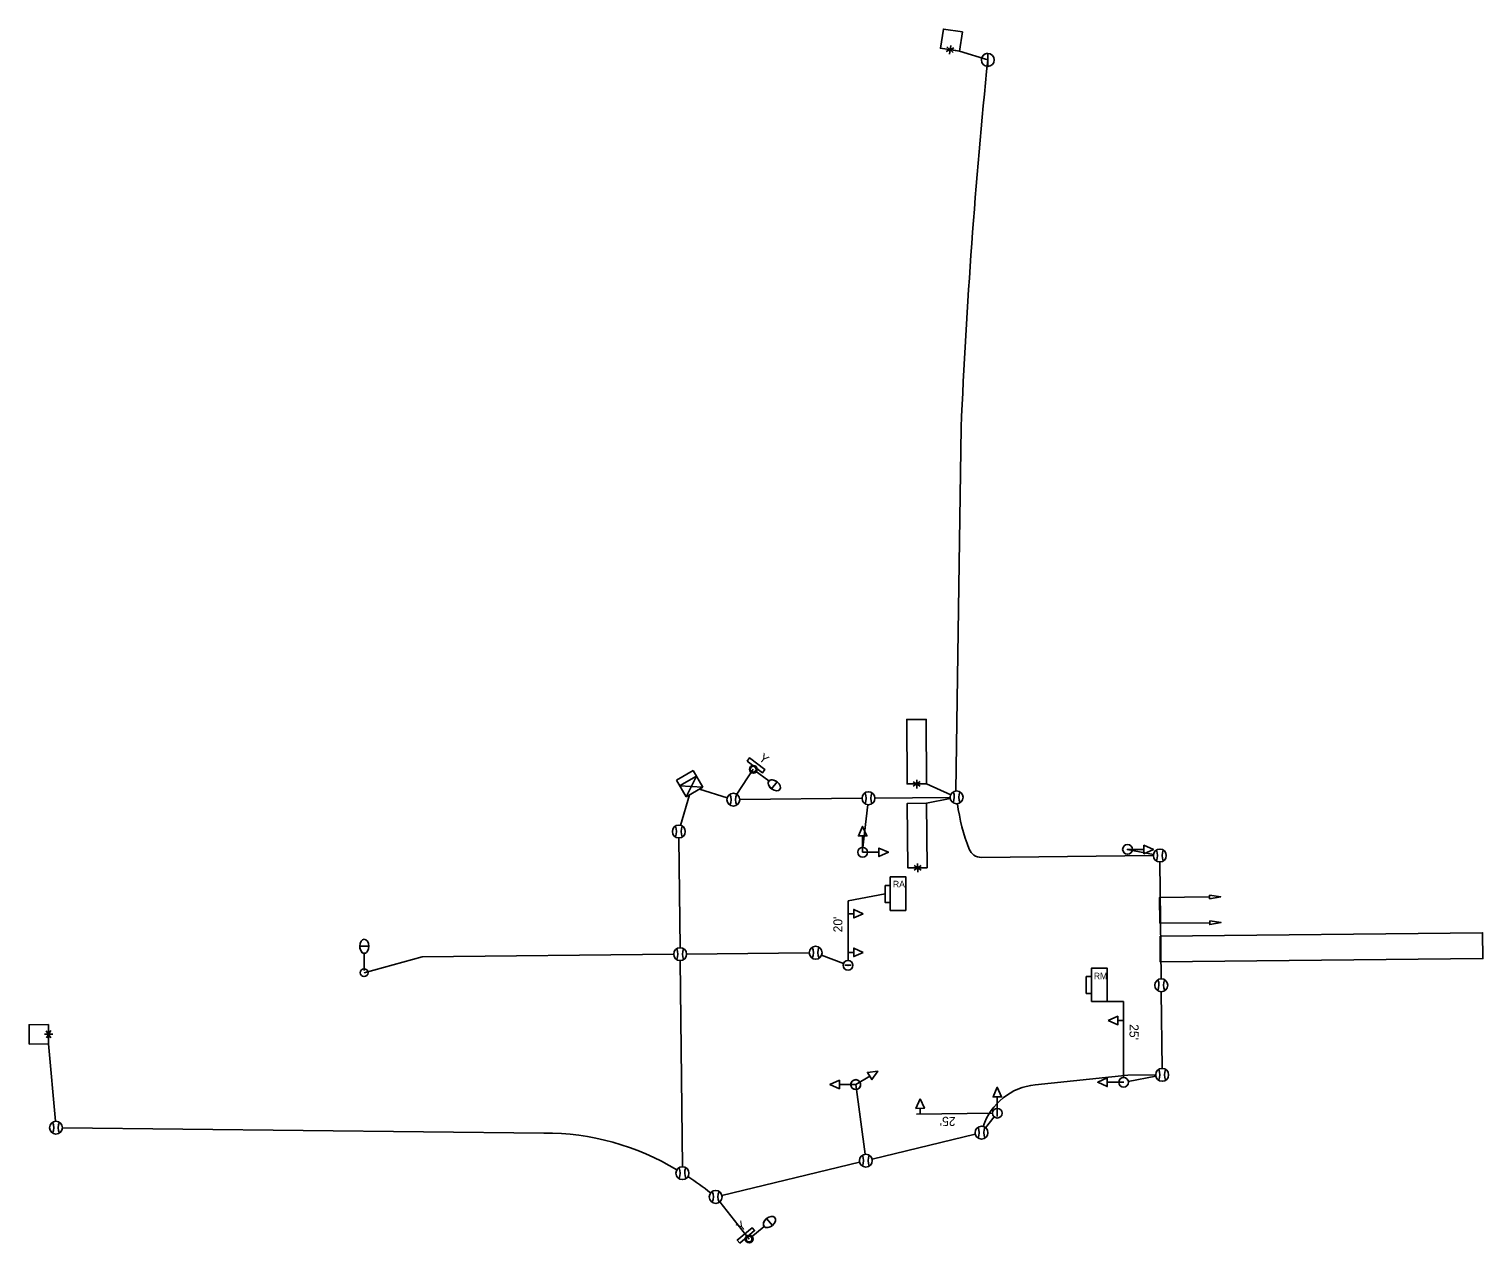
# Model space of a CAD drawing. Extents: x 596176 to 605330, y 332416 to 402398.
# Drawn here: x 602359.2 to 602809.7, y 387543.7 to 387920.7 of the extents above; entities that cross this region are included whole.
import ezdxf

# ---------------------------------------------------------------- set-up
doc = ezdxf.new("R2010")
doc.units = 0
for name, color, linetype in [('P_LTG', 7, 'Continuous'), ('P_SIG', 7, 'Continuous'), ('P_SIG_Bold', 7, 'Continuous'), ('P_SIG_Conduit', 7, 'Continuous'), ('P_SIG_Loops', 7, 'Continuous')]:
    doc.layers.add(name, color=color, linetype=linetype)

# ---------------------------------------------------------------- blocks, each defined once
blk = doc.blocks.new('_U309')
at = {"layer": 'P_SIG_Bold'}
for p, q in [((-3, 0), (-0.1, 0)), ((-0.1, 0.1), (0.1, -0.1)), ((0.1, 0.1), (-0.1, -0.1))]:
    blk.add_line(p, q, dxfattribs=at)
blk.add_circle((0, 0), 0.114, dxfattribs=at)
blk.add_text("40'", height=0.213, dxfattribs=at).set_placement((-1.9, 0.1))
blk = doc.blocks.new('_U321')
at = {"layer": 'P_LTG'}
for p, q in [((4.3, 25.1), (-4.1, 25.1)), ((0, 2.3), (0, 18.4))]:
    blk.add_line(p, q, dxfattribs=at)
blk.add_circle((0, 0.1), 3.68, dxfattribs=at)
blk.add_ellipse((0.1, 25.1), major_axis=(0, 6.65), ratio=0.636439, dxfattribs=at)
blk.add_ellipse((0.1, 25.1), major_axis=(0, 6.65), ratio=0.636439, start_param=1.570796, end_param=4.712389, dxfattribs=at)
blk = doc.blocks.new('_U322')
at = {"layer": 'P_LTG'}
for p, q in [((4.3, 25.1), (-4.1, 25.1)), ((0, 2.3), (0, 18.4))]:
    blk.add_line(p, q, dxfattribs=at)
blk.add_circle((0, 0.1), 3.68, dxfattribs=at)
blk.add_ellipse((0.1, 25.1), major_axis=(0, 6.65), ratio=0.636439, dxfattribs=at)
blk.add_ellipse((0.1, 25.1), major_axis=(0, 6.65), ratio=0.636439, start_param=1.570796, end_param=4.712389, dxfattribs=at)

msp = doc.modelspace()

# ---------------------------------------------------------------- linework, layer by layer
at = {"layer": 'P_SIG'}
for p, q in [((602656.31, 387913.11), (602656.29, 387909.11)), ((602581.71, 387693.74), (602582.44, 387694.7)), ((602586.49, 387690.11), (602581.71, 387693.74)), ((602582.44, 387694.7), (602587.22, 387691.06)), ((602559.78, 387687.78), (602564.96, 387690.8)), ((602562.8, 387682.59), (602559.78, 387687.78)), ((602560.79, 387686.05), (602565.97, 387689.07)), ((602562.8, 387682.59), (602565.97, 387689.07)), ((602564.96, 387690.8), (602567.99, 387685.62)), ((602587.22, 387691.06), (602586.49, 387690.11)), ((602567.99, 387685.62), (602560.79, 387686.05)), ((602567.99, 387685.62), (602562.8, 387682.59)), ((602617.5, 387670.51), (602617.49, 387665.46)), ((602622.55, 387665.44), (602617.49, 387665.46)), ((602704.66, 387666.31), (602699.6, 387666.33)), ((602624.45, 387652.53), (602612.98, 387650.41)), ((602614.75, 387646.41), (602612.98, 387646.41)), ((602614.77, 387634.41), (602612.99, 387634.41)), ((602693.26, 387619.22), (602698.37, 387619.13)), ((602696.6, 387613.29), (602698.37, 387613.31)), ((602610.31, 387593.44), (602615.37, 387593.43)), ((602619.69, 387596.07), (602615.37, 387593.43)), ((602693.31, 387594.14), (602698.37, 387594.13)), ((602659.25, 387589.61), (602659.24, 387584.55)), ((602635.33, 387586.07), (602635.35, 387584.3)), ((602578.65, 387545.19), (602583.24, 387549.05)), ((602584.01, 387548.13), (602579.42, 387544.27)), ((602583.24, 387549.05), (602584.01, 387548.13)), ((602579.42, 387544.27), (602578.65, 387545.19))]:
    msp.add_line(p, q, dxfattribs=at)
for points in [[(602656.29, 387909.11), (602656.31, 387913.11)], [(602617.5, 387673.47), (602618.82, 387670.51), (602616.18, 387670.51), (602617.5, 387673.47)], [(602618.82, 387670.51), (602617.5, 387673.47), (602616.18, 387670.51), (602618.82, 387670.51)], [(602625.51, 387665.44), (602622.55, 387664.13), (602622.55, 387666.76), (602625.51, 387665.44)], [(602622.55, 387664.13), (602625.51, 387665.44), (602622.55, 387666.76), (602622.55, 387664.13)], [(602707.62, 387666.31), (602704.66, 387665), (602704.66, 387667.63), (602707.62, 387666.31)], [(602704.66, 387665), (602707.62, 387666.31), (602704.66, 387667.63), (602704.66, 387665)], [(602622.21, 387597.62), (602620.38, 387594.95), (602619, 387597.19), (602622.21, 387597.62)], [(602620.38, 387594.95), (602622.21, 387597.62), (602619, 387597.19), (602620.38, 387594.95)], [(602607.35, 387593.44), (602610.31, 387594.76), (602610.31, 387592.12), (602607.35, 387593.44)], [(602610.31, 387594.76), (602607.35, 387593.44), (602610.31, 387592.12), (602610.31, 387594.76)], [(602659.25, 387592.57), (602660.57, 387589.61), (602657.93, 387589.61), (602659.25, 387592.57)], [(602659.25, 387592.57), (602660.57, 387589.61), (602657.93, 387589.61), (602659.25, 387592.57)], [(602660.57, 387589.61), (602659.25, 387592.57), (602657.93, 387589.61), (602660.57, 387589.61)], [(602690.35, 387594.14), (602693.31, 387595.46), (602693.31, 387592.82), (602690.35, 387594.14)], [(602690.35, 387594.14), (602693.31, 387595.46), (602693.31, 387592.82), (602690.35, 387594.14)], [(602693.31, 387595.46), (602690.35, 387594.14), (602693.31, 387592.82), (602693.31, 387595.46)]]:
    msp.add_lwpolyline(points, dxfattribs=at)
for points in [[(602581.71, 387693.74), (602582.44, 387694.7), (602587.22, 387691.06), (602586.49, 387690.11)], [(602630.91, 387647.44), (602630.91, 387657.79), (602626.08, 387657.79), (602626.08, 387647.44)], [(602624.45, 387655.17), (602626.05, 387655.17), (602626.05, 387649.89), (602624.45, 387649.89)], [(602617.71, 387646.41), (602614.75, 387645.09), (602614.75, 387647.72)], [(602617.72, 387634.41), (602614.77, 387633.09), (602614.77, 387635.72)], [(602693.26, 387619.22), (602693.26, 387629.56), (602688.44, 387629.56), (602688.44, 387619.22)], [(602686.81, 387626.94), (602688.4, 387626.94), (602688.4, 387621.67), (602686.81, 387621.67)], [(602693.64, 387613.26), (602696.58, 387614.61), (602696.61, 387611.97)], [(602635.3, 387589.03), (602636.65, 387586.08), (602634.01, 387586.05)], [(602579.42, 387544.27), (602578.65, 387545.19), (602583.24, 387549.05), (602584.01, 387548.13)]]:
    msp.add_lwpolyline(points, close=True, dxfattribs=at)
for centre, radius in [((602656.3, 387911.11), 2), ((602583.57, 387691.2), 0.9), ((602577.43, 387681.75), 2), ((602619.31, 387682.19), 2), ((602646.62, 387682.48), 2), ((602560.54, 387671.88), 2), ((602617.49, 387665.46), 1.52), ((602617.49, 387665.46), 1.52), ((602617.49, 387665.46), 1.52), ((602617.49, 387665.46), 1.52), ((602617.49, 387665.46), 1.52), ((602617.49, 387665.46), 1.52), ((602699.6, 387666.33), 1.52), ((602699.6, 387666.33), 1.52), ((602699.6, 387666.33), 1.52), ((602709.62, 387664.44), 2), ((602560.94, 387633.86), 2), ((602602.94, 387634.3), 2), ((602710.05, 387624.22), 2), ((602710.34, 387596.44), 2), ((602615.37, 387593.43), 1.52), ((602615.37, 387593.43), 1.52), ((602615.37, 387593.43), 1.52), ((602615.37, 387593.43), 1.52), ((602615.37, 387593.43), 1.52), ((602615.37, 387593.43), 1.52), ((602367.5, 387580.05), 2), ((602654.35, 387578.5), 2), ((602618.5, 387569.84), 2), ((602561.66, 387565.95), 2), ((602571.96, 387558.6), 2), ((602582.3, 387545.52), 0.9)]:
    msp.add_circle(centre, radius, dxfattribs=at)
for centre, radius, start, end in [((602656.3, 387911.11), 2, 89.7008, 180), ((602656.3, 387911.11), 2, 180, 269.7008), ((602572.36, 387681.78), 4.36, 336.6741, 22.5272), ((602582.5, 387681.79), 4.36, 157.5751, 203.4282), ((602614.24, 387682.23), 4.36, 336.6741, 22.5272), ((602624.38, 387682.24), 4.36, 157.5751, 203.4282), ((602641.55, 387682.52), 4.36, 336.6741, 22.5272), ((602651.69, 387682.53), 4.36, 157.5751, 203.4282), ((602555.46, 387671.91), 4.36, 336.6741, 22.5272), ((602565.61, 387671.92), 4.36, 157.5751, 203.4282), ((602617.49, 387665.46), 1.52, 0, 180), ((602617.49, 387665.46), 1.52, 90, 270), ((602617.49, 387665.46), 1.52, 180, 0), ((602617.49, 387665.46), 1.52, 270, 90), ((602699.6, 387666.33), 1.52, 0, 180), ((602699.6, 387666.33), 1.52, 180, 0), ((602704.55, 387664.47), 4.36, 336.6741, 22.5272), ((602714.69, 387664.48), 4.36, 157.5751, 203.4282), ((602555.87, 387633.89), 4.36, 336.6741, 22.5272), ((602566.01, 387633.9), 4.36, 157.5751, 203.4282), ((602597.87, 387634.34), 4.36, 336.6741, 22.5272), ((602608.01, 387634.35), 4.36, 157.5751, 203.4282), ((602704.98, 387624.26), 4.36, 336.6741, 22.5272), ((602715.12, 387624.27), 4.36, 157.5751, 203.4282), ((602705.27, 387596.48), 4.36, 336.6741, 22.5272), ((602715.41, 387596.48), 4.36, 157.5751, 203.4282), ((602615.37, 387593.43), 1.52, 0, 180), ((602615.37, 387593.43), 1.52, 31.5799, 211.5799), ((602615.37, 387593.43), 1.52, 180, 0), ((602615.37, 387593.43), 1.52, 211.5799, 31.5799), ((602362.43, 387580.09), 4.36, 336.6741, 22.5272), ((602372.57, 387580.09), 4.36, 157.5751, 203.4282), ((602649.28, 387578.54), 4.36, 336.6741, 22.5272), ((602659.42, 387578.55), 4.36, 157.5751, 203.4282), ((602613.43, 387569.88), 4.36, 336.6741, 22.5272), ((602623.57, 387569.89), 4.36, 157.5751, 203.4282), ((602556.59, 387565.98), 4.36, 336.6741, 22.5272), ((602566.73, 387565.99), 4.36, 157.5751, 203.4282), ((602566.89, 387558.64), 4.36, 336.6741, 22.5272), ((602577.03, 387558.65), 4.36, 157.5751, 203.4282)]:
    msp.add_arc(centre, radius, start, end, dxfattribs=at)
at = {"layer": 'P_SIG_Bold'}
for p, q in [((602612.98, 387650.41), (602612.98, 387631.91)), ((602698.37, 387619.13), (602698.37, 387595.63)), ((602634.24, 387584.29), (602657.74, 387584.53))]:
    msp.add_line(p, q, dxfattribs=at)
for centre in [(602612.98, 387630.41), (602698.37, 387594.13), (602659.24, 387584.55)]:
    msp.add_circle(centre, 1.5, dxfattribs=at)
at = {"layer": 'P_SIG_Conduit'}
for p, q in [((602578.47, 387683.46), (602583.59, 387691.19)), ((602563.86, 387683.21), (602561.1, 387673.79)), ((602575.5, 387682.29), (602566.95, 387685.01)), ((602621.31, 387682.21), (602644.62, 387682.46)), ((602617.31, 387682.17), (602579.43, 387681.77)), ((602617.57, 387666.95), (602619.08, 387680.21)), ((602560.56, 387669.83), (602560.92, 387635.86)), ((602699.51, 387666.33), (602707.66, 387664.8)), ((602710.03, 387626.22), (602709.64, 387662.44)), ((602562.94, 387633.88), (602600.94, 387634.28)), ((602604.8, 387633.58), (602611.58, 387630.95)), ((602560.96, 387631.86), (602561.64, 387567.95)), ((602710.32, 387598.44), (602710.07, 387622.2)), ((602618.24, 387571.83), (602615.37, 387593.43)), ((602708.38, 387596.06), (602699.84, 387594.41)), ((602655.61, 387580.06), (602658.3, 387583.38)), ((602620.45, 387570.31), (602652.41, 387578.03)), ((602573.91, 387559.07), (602616.56, 387569.37)), ((602573.2, 387557.04), (602582.32, 387545.53))]:
    msp.add_line(p, q, dxfattribs=at)
for points in [[(602648.03, 387797.12), (602646.43, 387684.47)], [(602654.3, 387663.85), (602707.62, 387664.41)], [(602463, 387628.07), (602480.98, 387633.01), (602558.94, 387633.83)], [(602670.96, 387593.36), (602699.65, 387596.32), (602708.34, 387596.42)], [(602369.5, 387580.01), (602518.69, 387578.39)]]:
    msp.add_lwpolyline(points, dxfattribs=at)
for centre, radius, start, end in [((604620.68, 387711.25), 1974.52, 174.19067, 177.50763), ((602710.24, 387689.44), 64, 188.0312, 201.0949), ((602654.26, 387667.85), 4, 201.0949, 270.6076), ((602672.92, 387574.46), 19, 95.905, 161.6722), ((602519.02, 387499.36), 79.03, 58.8144, 90.2371), ((602514.12, 387488.35), 91, 51.794, 57.2486)]:
    msp.add_arc(centre, radius, start, end, dxfattribs=at)
at = {"layer": 'P_SIG_Loops'}
for p, q in [((602645.78, 387914.86), (602643.41, 387913.77)), ((602645.57, 387913.42), (602643.63, 387915.14)), ((602644.4, 387912.94), (602644.8, 387915.58)), ((602644.59, 387914.3), (602647.55, 387913.85)), ((602647.55, 387913.85), (602656.3, 387911.11)), ((602635.36, 387687.37), (602633.19, 387685.93)), ((602635.37, 387685.92), (602633.19, 387687.32)), ((602634.29, 387685.26), (602634.28, 387687.94)), ((602634.26, 387686.63), (602637.26, 387686.64)), ((602637.26, 387686.67), (602644.79, 387683.3)), ((602644.66, 387682.1), (602637.33, 387680.67)), ((602635.65, 387659.93), (602633.46, 387661.31)), ((602635.63, 387661.38), (602633.47, 387659.93)), ((602634.57, 387659.26), (602634.54, 387661.94)), ((602634.54, 387660.64), (602637.54, 387660.67)), ((602365.19, 387609.03), (602365.16, 387612.03)), ((602366.56, 387609.06), (602363.89, 387609.03)), ((602364.45, 387610.11), (602365.9, 387607.95)), ((602365.9, 387610.14), (602364.52, 387607.95)), ((602365.22, 387606.03), (602367.32, 387582.04))]:
    msp.add_line(p, q, dxfattribs=at)
for points in [[(602647.55, 387913.85), (602648.45, 387919.78), (602642.52, 387920.68), (602641.62, 387914.75)], [(602637.26, 387686.64), (602637.2, 387706.64), (602631.2, 387706.63), (602631.26, 387686.63)], [(602637.54, 387660.67), (602637.33, 387680.67), (602631.33, 387680.6), (602631.54, 387660.6)], [(602725, 387652.18), (602728.51, 387651.63), (602725.01, 387651.01)], [(602725.08, 387644.18), (602728.59, 387643.63), (602725.1, 387643.01)], [(602709.67, 387639.43), (602709.75, 387631.43), (602809.75, 387632.49), (602809.66, 387640.49)], [(602365.16, 387612.03), (602359.16, 387611.96), (602359.22, 387605.96), (602365.22, 387606.03)]]:
    msp.add_lwpolyline(points, close=True, dxfattribs=at)
for points in [[(602725.01, 387651.59), (602709.54, 387651.43)], [(602709.54, 387651.43), (602709.54, 387651.43), (602709.63, 387643.43), (602709.63, 387643.43)], [(602725.09, 387643.6), (602709.63, 387643.43)]]:
    msp.add_lwpolyline(points, dxfattribs=at)

# ---------------------------------------------------------------- block references
at = {"layer": 'P_LTG', "xscale": 0.32808333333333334}
for name, p, yscale, rotation in [('_U321', (602583.59, 387691.19), 0.3280833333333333, -127.08364887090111), ('_U309', (602699.6, 387666.31), 0.32808333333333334, 180), ('_U309', (602612.98, 387630.41), 0.32808333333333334, 180), ('_U309', (602659.24, 387584.55), 0.32808333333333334, 90), ('_U321', (602582.32, 387545.53), 0.3280833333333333, -49.87014046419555)]:
    msp.add_blockref(name, p, dxfattribs=dict(at, yscale=yscale, rotation=rotation))
at = {"layer": 'P_LTG', "xscale": 0.32808333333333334, "yscale": 0.32808333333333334}
for name, p in [('_U322', (602463, 387628.07)), ('_U309', (602612.98, 387630.41)), ('_U309', (602698.37, 387594.18))]:
    msp.add_blockref(name, p, dxfattribs=at)

# ---------------------------------------------------------------- texts
at = {"layer": 'P_SIG'}
for s, height, rotation, p in [('Y', 2.8, 322.7651, (602585.1, 387694.13)), ('RA', 2, 360, (602626.9, 387654.6)), ('RM', 2, 360, (602689.16, 387626.1)), ('Y', 2.8, 39.9787, (602579.79, 387547.66))]:
    msp.add_text(s, height=height, rotation=rotation, dxfattribs=at).set_placement(p)
at = {"layer": 'P_SIG_Bold'}
for s, rotation, p in [("20'", 90, (602611.23, 387640.62)), ("25'", 269.3924, (602700.25, 387612.16)), ("25'", 179.4938, (602646.31, 387583.4))]:
    msp.add_text(s, height=2.8, rotation=rotation, dxfattribs=at).set_placement(p)

doc.saveas('drawing.dxf')
